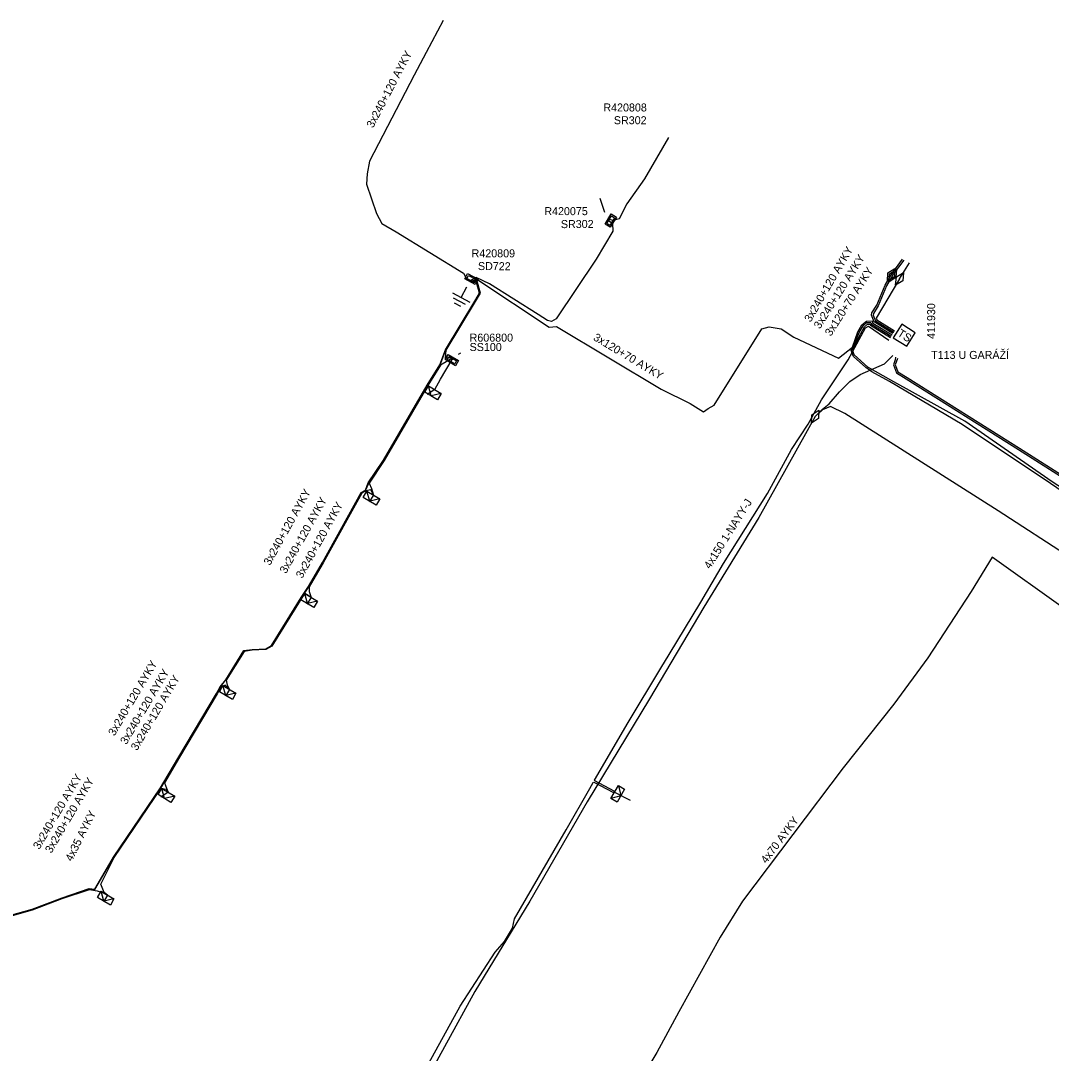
# Model space of a CAD drawing. Extents: x -540028 to -538776, y -1157064 to -1155670.
# Drawn here: x -539322.6 to -539193.8, y -1155798.8 to -1155669.8 of the extents above; entities that cross this region are included whole.
import ezdxf

# ---------------------------------------------------------------- set-up
doc = ezdxf.new("R2010")
doc.units = 0
for name, color, linetype in [('Vrstva 15', 7, 'Continuous'), ('Vrstva 19', 7, 'Continuous'), ('Vrstva 2', 7, 'Continuous'), ('Vrstva 25', 7, 'Continuous'), ('Vrstva 26', 7, 'Continuous'), ('Vrstva 27', 7, 'Continuous'), ('Vrstva 28', 7, 'Continuous'), ('Vrstva 29', 7, 'Continuous'), ('Vrstva 30', 7, 'Continuous'), ('Vrstva 31', 7, 'Continuous'), ('Vrstva 5', 7, 'Continuous'), ('Vrstva 59', 7, 'Continuous'), ('Vrstva 6', 7, 'Continuous'), ('Vrstva 9', 7, 'Continuous')]:
    doc.layers.add(name, color=color, linetype=linetype)

# ---------------------------------------------------------------- blocks, each defined once
blk = doc.blocks.new('17')
at = {"layer": 'Vrstva 2'}
blk.add_lwpolyline([(-1.875, 0), (0, 0.9375), (1.875, 0), (0, -0.9375)], close=True, dxfattribs=at)
blk = doc.blocks.new('30')
at = {"layer": 'Vrstva 2'}
blk.add_lwpolyline([(-2, 0), (2, 0), (2, 4), (-2, 4)], close=True, dxfattribs=at)
blk.add_text('TS', height=2, dxfattribs=at).set_placement((-1.598, 1))
blk = doc.blocks.new('132')
at = {"layer": 'Vrstva 2'}
for points in [[(-1.5, 1.5), (1.5, 1.5), (1.5, 0), (-1.5, 0)], [(-1.1, 1.2), (1.1, 1.2), (1.1, 0.3), (-1.1, 0.3)]]:
    blk.add_lwpolyline(points, close=True, dxfattribs=at)
blk = doc.blocks.new('23')
at = {"layer": 'Vrstva 2'}
blk.add_lwpolyline([(1.875, -1.8), (-1.875, -1.8), (-1.875, 0), (1.875, 0)], close=True, dxfattribs=at)
blk.add_lwpolyline([(1.875, 0), (0, -1.8), (-1.875, 0)], dxfattribs=at)
blk = doc.blocks.new('11')
at = {"layer": 'Vrstva 2'}
for p, q in [((0, -4.3), (0, -1.3)), ((-2.5, -4.3), (2.5, -4.3)), ((-1.7, -5.3), (1.7, -5.3)), ((-0.9, -6.3), (0.9, -6.3))]:
    blk.add_line(p, q, dxfattribs=at)

msp = doc.modelspace()

# ---------------------------------------------------------------- linework, layer by layer
at = {"layer": 'Vrstva 5'}
for points in [[(-539269.78, -1155669.79), (-539271.88, -1155673.79), (-539273.39, -1155676.59), (-539279, -1155687.33), (-539279.28, -1155688.91), (-539279.37, -1155690.24), (-539278.09, -1155693.89), (-539277.45, -1155695.15), (-539275.66, -1155696.17), (-539267.22, -1155701.32), (-539266.83, -1155702.14)], [(-539241.62, -1155684.41), (-539244.6, -1155689.54), (-539246.81, -1155692.69), (-539247.78, -1155694.54), (-539248.55, -1155694.75), (-539249.12, -1155694.58)], [(-539249.19, -1155694.69), (-539248.6, -1155695.14), (-539248.56, -1155696.1), (-539250.65, -1155699.57), (-539255.64, -1155707.03), (-539256.22, -1155707.36), (-539256.74, -1155707.23), (-539257.9, -1155706.52), (-539264, -1155702.66), (-539265.64, -1155701.87), (-539266.51, -1155702.32)], [(-539213.78, -1155701.55), (-539212.38, -1155699.59)], [(-539213.6, -1155701.65), (-539212.16, -1155699.71)], [(-539212.73, -1155702.04), (-539211.48, -1155700.06)], [(-539268.63, -1155711.8), (-539268.83, -1155711.91), (-539269.12, -1155711.94), (-539269.47, -1155711.95), (-539269.4, -1155710.94), (-539265.73, -1155704.87), (-539265.13, -1155703.85), (-539265.58, -1155702.2), (-539266.2, -1155702.48)], [(-539266.38, -1155702.39), (-539265.58, -1155702.08), (-539256.53, -1155708.08), (-539255.63, -1155707.98), (-539242.54, -1155715.83), (-539238.89, -1155717.61), (-539237.25, -1155718.65), (-539236.65, -1155718.25), (-539235.91, -1155717.82), (-539229.95, -1155708.29), (-539229.02, -1155708.05), (-539227.52, -1155708.3), (-539225.96, -1155709.35), (-539220.38, -1155711.95), (-539218.62, -1155710.58), (-539217.94, -1155708.67), (-539217.45, -1155707.78), (-539216.88, -1155707.32), (-539216.17, -1155707.3), (-539216.06, -1155707.57), (-539213.66, -1155709.04)], [(-539213.56, -1155708.88), (-539215.9, -1155707.43), (-539216.25, -1155706.59), (-539216.18, -1155706.28), (-539215.59, -1155705.33), (-539214.53, -1155702.82), (-539213.78, -1155701.55)], [(-539213.6, -1155701.65), (-539214.35, -1155702.92), (-539215.41, -1155705.43), (-539216, -1155706.36), (-539216.04, -1155706.57), (-539215.74, -1155707.3), (-539213.45, -1155708.71)], [(-539212.73, -1155702.04), (-539215.66, -1155706.96), (-539215.58, -1155707.16), (-539213.35, -1155708.53)], [(-539323.97, -1155781.59), (-539321.14, -1155780.78), (-539317.41, -1155779.36), (-539314.01, -1155778.22), (-539313.33, -1155778.29), (-539310.97, -1155774.28), (-539305.11, -1155765.62), (-539304.7, -1155764.94), (-539302.8, -1155761.74), (-539298.12, -1155753.83), (-539297.65, -1155753), (-539296.96, -1155752.12), (-539294.7, -1155748.49), (-539293.65, -1155748.34), (-539291.95, -1155748.26), (-539291.23, -1155747.83), (-539287.54, -1155741.85), (-539286.6, -1155740.48), (-539284.86, -1155737.47), (-539280.02, -1155728.73), (-539279.49, -1155728.44), (-539279.13, -1155727.53), (-539277.25, -1155724.69), (-539271.77, -1155715.33), (-539270.2, -1155712.78), (-539269.49, -1155710.91), (-539265.82, -1155704.82), (-539265.24, -1155703.84), (-539265.65, -1155702.34), (-539266, -1155702.59)], [(-539323.94, -1155781.64), (-539321.12, -1155780.82), (-539317.4, -1155779.41), (-539314.01, -1155778.27), (-539313.31, -1155778.34), (-539310.93, -1155774.3), (-539305.07, -1155765.65), (-539304.66, -1155764.97), (-539302.76, -1155761.77), (-539298.08, -1155753.85), (-539297.61, -1155753.02), (-539296.92, -1155752.15), (-539294.67, -1155748.54), (-539293.65, -1155748.39), (-539291.93, -1155748.31), (-539291.2, -1155747.87), (-539287.5, -1155741.88), (-539286.56, -1155740.51), (-539284.81, -1155737.49), (-539279.98, -1155728.77), (-539279.47, -1155728.49), (-539279.08, -1155727.55), (-539277.21, -1155724.71), (-539271.73, -1155715.36), (-539270.15, -1155712.8), (-539269.45, -1155710.93), (-539265.78, -1155704.85), (-539265.18, -1155703.84), (-539265.61, -1155702.27), (-539266.1, -1155702.54)], [(-539271.57, -1155800.03), (-539267.67, -1155792.9), (-539263.27, -1155786.16), (-539262.09, -1155784.83), (-539261.1, -1155783.16), (-539260.88, -1155781.99), (-539254.39, -1155770.86), (-539251.46, -1155765.71), (-539251.02, -1155764.95), (-539250.94, -1155764.94), (-539248.48, -1155766.2), (-539248.35, -1155766.16), (-539248.39, -1155766.03), (-539250.83, -1155764.77), (-539250.87, -1155764.68), (-539246.65, -1155757.47), (-539242.56, -1155750.7), (-539241.52, -1155748.98), (-539237.56, -1155742.43), (-539234.73, -1155737.59), (-539229.23, -1155728.85), (-539226.25, -1155723.37), (-539224.14, -1155720.19), (-539222.5, -1155717.15), (-539219.14, -1155712.15), (-539216.99, -1155708.15), (-539216.61, -1155707.95), (-539214.07, -1155709.69)], [(-539182.46, -1155753.72), (-539181.11, -1155750.42), (-539178.34, -1155745.57), (-539176.63, -1155741.1), (-539176.61, -1155740.52), (-539176.87, -1155739.86), (-539179.23, -1155738.01), (-539187.39, -1155732.01), (-539193.88, -1155727.61), (-539204.91, -1155720.23), (-539213.97, -1155714.89), (-539216.2, -1155713.66), (-539216.94, -1155713.13), (-539218.5, -1155711.74), (-539218.76, -1155711), (-539218.49, -1155710.49), (-539217.76, -1155708.77), (-539217.29, -1155707.91), (-539216.81, -1155707.52), (-539216.3, -1155707.51), (-539216.22, -1155707.7), (-539213.77, -1155709.22)], [(-539182.35, -1155753.78), (-539180.98, -1155750.51), (-539178.12, -1155745.74), (-539176.3, -1155741.11), (-539176.13, -1155740.44), (-539176.57, -1155739.76), (-539179.05, -1155737.88), (-539187.17, -1155731.63), (-539193.67, -1155727.39), (-539204.57, -1155719.84), (-539213.84, -1155714.69), (-539216.71, -1155713.1), (-539218.42, -1155711.55), (-539218.57, -1155711.04), (-539218.45, -1155710.54), (-539217.58, -1155708.87), (-539217.13, -1155708.04), (-539216.74, -1155707.72), (-539216.43, -1155707.71), (-539216.38, -1155707.84), (-539213.87, -1155709.39)], [(-539268.5, -1155711.88), (-539270.11, -1155712.82), (-539271.69, -1155715.38), (-539277.17, -1155724.74), (-539279.04, -1155727.57), (-539278.73, -1155728.23), (-539278.5, -1155729.05), (-539278.83, -1155728.4), (-539279.45, -1155728.53), (-539279.94, -1155728.8), (-539284.77, -1155737.52), (-539286.52, -1155740.54), (-539286.52, -1155741.12), (-539286.28, -1155741.84), (-539286.64, -1155741.61), (-539287.07, -1155741.35), (-539287.45, -1155741.9), (-539291.18, -1155747.92), (-539291.92, -1155748.36), (-539293.64, -1155748.44), (-539294.64, -1155748.59), (-539296.88, -1155752.19), (-539296.78, -1155752.81), (-539296.49, -1155753.33), (-539297.01, -1155752.8), (-539297.57, -1155753.05), (-539298.04, -1155753.88), (-539302.72, -1155761.79), (-539304.61, -1155764.99), (-539304.37, -1155765.66), (-539304.13, -1155766.19)], [(-539270.82, -1155715.89), (-539270.1, -1155714.57), (-539268.65, -1155712.13), (-539268.37, -1155711.96)], [(-539223.28, -1155719.26), (-539222.36, -1155718.33), (-539221.52, -1155717.64), (-539220.23, -1155716.15), (-539218.94, -1155714.86), (-539217.64, -1155713.98), (-539214.61, -1155712.66), (-539213.56, -1155711.62)], [(-539212.99, -1155711.99), (-539213.28, -1155712.79), (-539213.24, -1155712.89), (-539212.95, -1155713.65), (-539211.8, -1155714.37), (-539197.75, -1155723.19), (-539191.25, -1155727.33), (-539180.96, -1155733.85), (-539171.79, -1155739.77), (-539167.53, -1155743.07), (-539166.04, -1155744.64), (-539164.69, -1155746.97), (-539163.93, -1155749.54), (-539163.86, -1155751.51), (-539164.08, -1155753.82), (-539165.06, -1155756.65), (-539168.59, -1155762.6), (-539169.26, -1155764.09), (-539170.27, -1155764.84), (-539170.54, -1155765.45), (-539170.89, -1155765.82), (-539171.33, -1155765.84), (-539171.89, -1155765.72)], [(-539223.28, -1155719.26), (-539230.33, -1155731.85), (-539237.2, -1155743.07), (-539243.97, -1155754.51), (-539251.76, -1155767.37), (-539258.93, -1155779.8), (-539265.81, -1155791.09), (-539273.41, -1155804.91), (-539284.01, -1155822.69), (-539288.74, -1155830.83), (-539295.21, -1155841.44), (-539300.56, -1155850.72), (-539301.46, -1155851.88), (-539302.26, -1155852.36), (-539303.21, -1155852.67), (-539308.77, -1155849.65), (-539314.79, -1155846.05), (-539324.41, -1155840.48)], [(-539192.27, -1155743.14), (-539201.17, -1155736.81), (-539203.79, -1155741.11), (-539209.21, -1155749.39), (-539213.43, -1155755.19), (-539219.77, -1155763.12), (-539232.36, -1155779.8), (-539235.17, -1155784.3), (-539240.34, -1155793.59), (-539243.08, -1155798.71), (-539248.89, -1155808.43), (-539254.81, -1155817.91), (-539259.8, -1155825.75), (-539264.72, -1155833.66), (-539269.12, -1155840.54), (-539272.15, -1155845.31), (-539274.08, -1155848.24), (-539274.59, -1155848.49), (-539279.21, -1155846.07), (-539284.75, -1155841.62), (-539286.66, -1155840.65), (-539287.04, -1155840.91), (-539287.88, -1155842.07)], [(-539323.91, -1155781.68), (-539321.1, -1155780.87), (-539317.38, -1155779.46), (-539314, -1155778.32), (-539313.04, -1155778.5), (-539312.15, -1155778.77), (-539311.73, -1155779.02), (-539312.13, -1155778.69), (-539312.56, -1155777.68), (-539310.89, -1155774.33), (-539305.03, -1155765.68), (-539304.45, -1155765.79), (-539304.13, -1155766.19)]]:
    msp.add_lwpolyline(points, dxfattribs=at)
at = {"layer": 'Vrstva 59'}
for points in [[(-539249.55, -1155693.77), (-539250.14, -1155692.03)], [(-539267.84, -1155711.46), (-539267.56, -1155711.27)], [(-539270.82, -1155715.89), (-539271.77, -1155716.49)], [(-539278.5, -1155729.05), (-539279.01, -1155729.91)], [(-539286.28, -1155741.84), (-539286.8, -1155742.7)], [(-539296.49, -1155753.33), (-539296.99, -1155754.19)], [(-539304.13, -1155766.19), (-539305.08, -1155766.78)], [(-539248.35, -1155766.16), (-539246.42, -1155767.17)], [(-539311.73, -1155779.02), (-539312.23, -1155779.89)]]:
    msp.add_lwpolyline(points, dxfattribs=at)
at = {"layer": 'Vrstva 9'}
for points in [[(-539213.25, -1155711.83), (-539213.27, -1155712.15), (-539213.49, -1155712.79), (-539213.11, -1155713.79), (-539211.9, -1155714.53), (-539197.85, -1155723.36), (-539191.35, -1155727.49)], [(-539170.07, -1155764.06), (-539165.55, -1155756.18), (-539165.11, -1155755.14), (-539165.42, -1155754.67), (-539167.71, -1155752.52), (-539173.43, -1155747.99), (-539178.39, -1155744.86), (-539191.27, -1155736.94), (-539200.41, -1155731.01), (-539219.59, -1155718.88), (-539221.38, -1155717.98), (-539222.35, -1155718.43), (-539222.95, -1155718.97)]]:
    msp.add_lwpolyline(points, dxfattribs=at)

# ---------------------------------------------------------------- block references
at = {"layer": 'Vrstva 15', "xscale": 0.5, "yscale": 0.5, "rotation": -28.610458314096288}
msp.add_blockref('11', (-539266.49, -1155702.49), dxfattribs=at)
at = {"layer": 'Vrstva 19'}
for p, xscale, yscale, rotation in [((-539213.78, -1155701.55), 0.5000000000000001, 0.4999999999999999, 59.42077225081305), ((-539213.6, -1155701.65), 0.5, 0.5, 59.451324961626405), ((-539212.73, -1155702.04), 0.49999999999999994, 0.5000000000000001, 57.731797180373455), ((-539223.28, -1155719.26), 0.5, 0.5, 60.76877226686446)]:
    msp.add_blockref('17', p, dxfattribs=dict(at, xscale=xscale, yscale=yscale, rotation=rotation))
at = {"layer": 'Vrstva 25', "xscale": 0.5, "yscale": 0.49999999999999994, "rotation": -32.51318338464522}
msp.add_blockref('30', (-539212.68, -1155709.94), dxfattribs=at)
at = {"layer": 'Vrstva 28', "xscale": 0.5, "yscale": 0.5}
for p, rotation in [((-539249.15, -1155694.58), -121.53916662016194), ((-539266.42, -1155702.4), -28.610458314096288), ((-539268.5, -1155711.88), 149.2700195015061)]:
    msp.add_blockref('132', p, dxfattribs=dict(at, rotation=rotation))
at = {"layer": 'Vrstva 31'}
for p, xscale, yscale, rotation in [((-539270.82, -1155715.89), 0.5, 0.5, -30.7299804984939), ((-539278.5, -1155729.05), 0.5, 0.5, -30.873177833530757), ((-539286.28, -1155741.84), 0.49999999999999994, 0.5000000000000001, -30.929163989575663), ((-539296.49, -1155753.33), 0.49999999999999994, 0.5000000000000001, -29.966291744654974), ((-539248.35, -1155766.16), 0.49999999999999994, 0.5000000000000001, 59.83734290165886), ((-539304.13, -1155766.19), 0.5000000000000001, 0.5, -31.34235829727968), ((-539311.73, -1155779.02), 0.5, 0.5, -30.338969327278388)]:
    msp.add_blockref('23', p, dxfattribs=dict(at, xscale=xscale, yscale=yscale, rotation=rotation))

# ---------------------------------------------------------------- texts
at = {"layer": 'Vrstva 26'}
msp.add_text('411930', height=1, rotation=90, dxfattribs=at).set_placement((-539208.28, -1155709.55))
at = {"layer": 'Vrstva 27'}
msp.add_text('T113 U GARÁŽÍ', height=1, dxfattribs=at).set_placement((-539208.78, -1155712.05))
at = {"layer": 'Vrstva 29'}
for s, p in [('R420808', (-539249.75, -1155681.14)), ('R420075', (-539257.13, -1155694.09)), ('R420809', (-539266.22, -1155699.36)), ('R606800', (-539266.47, -1155709.89))]:
    msp.add_text(s, height=1, dxfattribs=at).set_placement(p)
at = {"layer": 'Vrstva 30'}
for s, rotation, p in [('SR302', 359.895, (-539248.44, -1155682.73)), ('SR302', 0.258, (-539255.06, -1155695.71)), ('SD722', 359.683, (-539265.43, -1155700.95))]:
    msp.add_text(s, height=1, rotation=rotation, dxfattribs=at).set_placement(p)
msp.add_text('SS100', height=1, dxfattribs=at).set_placement((-539266.47, -1155711.06))
at = {"layer": 'Vrstva 6'}
for s, rotation, p in [('3x240+120 AYKY', 62.425, (-539278.54, -1155683.28)), ('3x240+120 AYKY', 59.667, (-539223.85, -1155707.53)), ('3x240+120 AYKY', 57.668, (-539222.69, -1155708.38)), ('3x120+70 AYKY', 57.151, (-539221.31, -1155709.28)), ('3x120+70 AYKY', 329.055, (-539251.1, -1155709.63)), ('3x240+120 AYKY', 61.028, (-539291.42, -1155737.92)), ('3x240+120 AYKY', 61.025, (-539289.41, -1155738.94)), ('3x240+120 AYKY', 61.021, (-539287.39, -1155739.54)), ('4x150 1-NAYY-J', 57.818, (-539236.42, -1155738.37)), ('3x240+120 AYKY', 59.385, (-539310.86, -1155759.22)), ('3x240+120 AYKY', 59.411, (-539309.36, -1155760.29)), ('3x240+120 AYKY', 59.411, (-539308.04, -1155761.06)), ('3x240+120 AYKY', 59.518, (-539320.25, -1155773.4)), ('3x240+120 AYKY', 59.521, (-539318.75, -1155773.87)), ('4x35 AYKY', 63.476, (-539316.18, -1155774.9)), ('4x70 AYKY', 52.955, (-539229.38, -1155775.16))]:
    msp.add_text(s, height=1, rotation=rotation, dxfattribs=at).set_placement(p)

doc.saveas('drawing.dxf')
